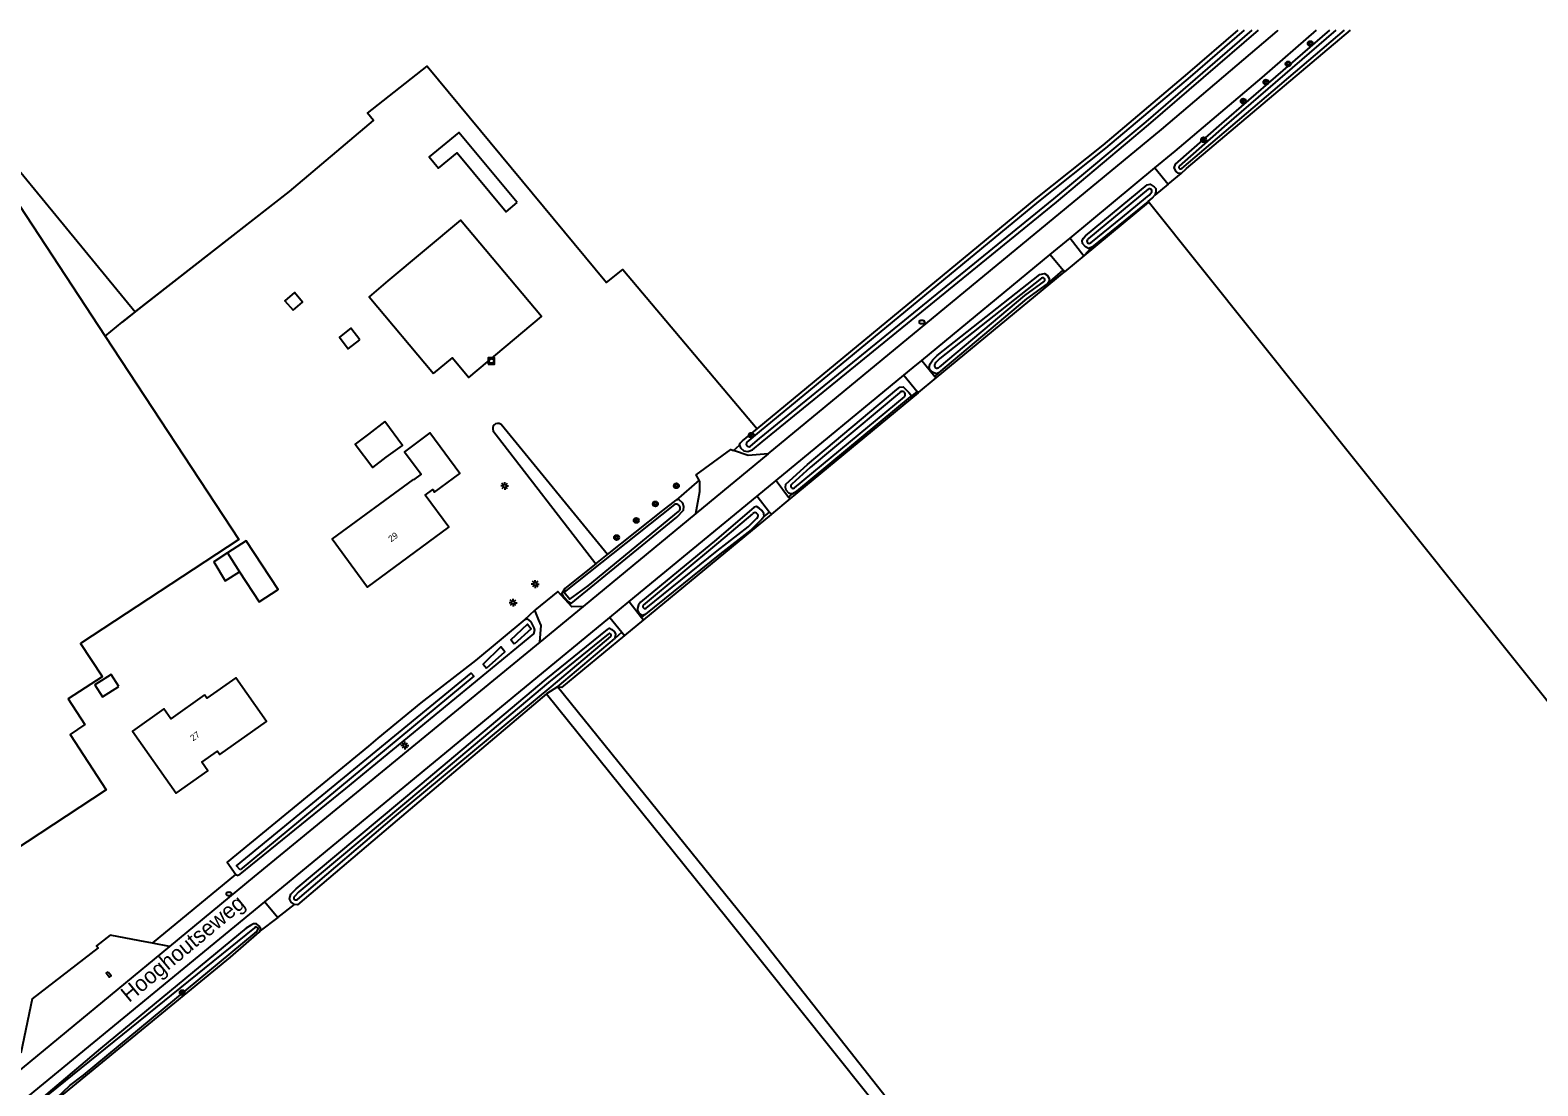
# Model space of a CAD drawing. Extents: x 141000 to 143000, y 400580 to 403500.
# Drawn here: x 142087.7 to 142326.5, y 403332.7 to 403500 of the extents above; entities that cross this region are included whole.
import ezdxf

# ---------------------------------------------------------------- set-up
doc = ezdxf.new("R2010")
doc.units = 0
for name, color, linetype in [('gg-afsc-erfafscheiding', 7, 'Continuous'), ('gg-afsc-hekwerk', 7, 'Continuous'), ('gg-anno-huisnummerreeks BGT', 7, 'Continuous'), ('gg-anno-openbare ruimte label', 7, 'Continuous'), ('gg-bbg-bijgebouw', 7, 'Continuous'), ('gg-bbg-hoofdgebouw', 7, 'Continuous'), ('gg-bbg-luifel en loopbrug', 7, 'Continuous'), ('gg-bbg-overig bouwwerk', 7, 'Continuous'), ('gg-knt-bronhoudergrens', 7, 'Continuous'), ('gg-knt-onverhard', 7, 'Continuous'), ('gg-knt-verharding', 7, 'Continuous'), ('gg-knt-verharding nz', 7, 'Continuous'), ('gg-kntw-bovenkant insteek waterloop', 7, 'Continuous'), ('gg-kntw-waterlijn', 7, 'Continuous'), ('gt-grn-groengrens', 7, 'Continuous'), ('gt-symb-boom', 7, 'Continuous'), ('gt-symb-brandkraan', 7, 'Continuous'), ('gt-symb-kolk center center', 7, 'Continuous'), ('gt-symb-lichtmast', 7, 'Continuous'), ('gt-symb-rioolschacht', 7, 'Continuous')]:
    doc.layers.add(name, color=color, linetype=linetype)

# ---------------------------------------------------------------- blocks, each defined once
blk = doc.blocks.new('gt0-BOOM')
at = {"layer": 'gt-symb-boom'}
for radius in [0.4, 0.2]:
    blk.add_circle((0, 0), radius, dxfattribs=at)
blk = doc.blocks.new('gt0-BR')
at = {"layer": 'gt-symb-brandkraan'}
for centre, radius, start, end in [((-0.24, 0), 0.206, 107.5669, 252.4331), ((0.6, -2.66), 3, 106.892, 107.5669), ((0, -0.69), 0.938, 73.108, 106.892), ((-0.6, -2.66), 3, 72.4331, 73.108), ((0.24, 0), 0.206, 287.567, 72.4331), ((0.6, 2.66), 3, 252.4331, 253.108), ((0, 0.69), 0.938, 253.108, 286.8921), ((-0.6, 2.66), 3, 286.8921, 287.567)]:
    blk.add_arc(centre, radius, start, end, dxfattribs=at)
blk = doc.blocks.new('gt0-RS')
at = {"layer": 'gt-symb-rioolschacht'}
blk.add_lwpolyline([(-0.5, -0.5), (0.5, -0.5), (0.5, 0.5), (-0.5, 0.5)], close=True, dxfattribs=at)
blk.add_circle((0, 0), 0.375, dxfattribs=at)
blk = doc.blocks.new('gt0-LMAST')
at = {"layer": 'gt-symb-lichtmast'}
for p, q in [((-0.18, 0.17), (-0.45, 0.44)), ((-0.01, 0.25), (-0.01, 0.62)), ((0.17, 0.17), (0.44, 0.44)), ((-0.26, 0), (-0.63, 0)), ((-0.18, -0.18), (-0.45, -0.45)), ((-0.01, -0.25), (-0.01, -0.63)), ((0.44, -0.45), (0.17, -0.18)), ((0.24, 0), (0.62, 0))]:
    blk.add_line(p, q, dxfattribs=at)
blk.add_circle((-0.01, 0), 0.25, dxfattribs=at)
blk = doc.blocks.new('gt0-KOLKCC')
at = {"layer": 'gt-symb-kolk center center'}
blk.add_lwpolyline([(-0.38, 0.2), (0.38, 0.2), (0.38, -0.2), (-0.38, -0.2)], close=True, dxfattribs=at)

msp = doc.modelspace()

# ---------------------------------------------------------------- linework, layer by layer
at = {"layer": 'gg-afsc-erfafscheiding'}
for p, q in [((142104.3, 403455.35), (142102.23, 403453.74)), ((142099.57, 403451.49), (142102.23, 403453.74)), ((142199.08, 403433.4), (142200.05, 403434.24)), ((142193.63, 403428.69), (142189.99, 403425.54)), ((142171.9, 403410.75), (142171.72, 403410.56)), ((142166.05, 403406.62), (142167.62, 403408.1))]:
    msp.add_line(p, q, dxfattribs=at)
at = {"layer": 'gg-afsc-hekwerk'}
for p, q in [((142102.23, 403453.74), (142128.76, 403474.43)), ((142264.76, 403472.67), (142254.57, 403464.23)), ((142254.57, 403464.23), (142251.54, 403461.72)), ((142228.32, 403442.56), (142208.04, 403425.74)), ((142208.04, 403425.74), (142205.09, 403423.3)), ((142184.83, 403406.55), (142181.83, 403404.07)), ((142181.83, 403404.07), (142171.86, 403395.83)), ((142107.06, 403355.32), (142120.24, 403366.21)), ((142107.06, 403355.32), (142105.02, 403355.7))]:
    msp.add_line(p, q, dxfattribs=at)
for points in [[(142251.54, 403461.72), (142251.44, 403461.64), (142231.17, 403444.91)], [(142231.17, 403444.91), (142228.34, 403442.58), (142228.32, 403442.56)], [(142205.09, 403423.3), (142205.05, 403423.27), (142184.83, 403406.55)], [(142142.75, 403387.82), (142141.26, 403386.57), (142118.87, 403368.2), (142120.24, 403366.21)], [(142105.02, 403355.7), (142100.36, 403356.59), (142098.19, 403354.93), (142098.46, 403354.58), (142087.98, 403346.52), (142086.18, 403337.91)]]:
    msp.add_lwpolyline(points, dxfattribs=at)
at = {"layer": 'gg-bbg-bijgebouw'}
for points in [[(142062.5, 403500), (142067.6, 403492.19), (142071.26, 403494.59), (142099.57, 403451.49)], [(142151.56, 403445.59), (142154.55, 403448.1), (142157.16, 403444.98), (142168.67, 403454.63), (142155.85, 403469.92), (142144.34, 403460.27), (142141.36, 403457.76), (142151.56, 403445.59)], [(142099.57, 403451.49), (142120.71, 403419.3), (142095.64, 403402.84), (142099.01, 403397.69), (142099.1, 403397.55), (142093.7, 403394.06), (142096.34, 403389.97), (142094, 403388.42), (142099.72, 403379.66), (142085.01, 403369.97)]]:
    msp.add_lwpolyline(points, dxfattribs=at)
at = {"layer": 'gg-bbg-hoofdgebouw'}
for points in [[(142148.41, 403428.75), (142148.36, 403428.83), (142135.49, 403419.38), (142141.13, 403411.73), (142154.01, 403421.26), (142150.26, 403426.33), (142151.44, 403427.2), (142151.73, 403426.8), (142155.75, 403429.77), (142151.01, 403436.18), (142146.99, 403433.2), (142149.61, 403429.63), (142148.41, 403428.75)], [(142115.28, 403394.67), (142109.94, 403390.9), (142108.84, 403392.46), (142103.87, 403388.95), (142110.82, 403379.11), (142115.83, 403382.65), (142114.87, 403384.01), (142117.36, 403385.77), (142117.73, 403385.26), (142125.1, 403390.46), (142120.23, 403397.36), (142115.65, 403394.14), (142115.28, 403394.67)]]:
    msp.add_lwpolyline(points, dxfattribs=at)
at = {"layer": 'gg-bbg-luifel en loopbrug'}
msp.add_line((142118.92, 403417.17), (142120.84, 403414.17), dxfattribs=at)
for points in [[(142143.84, 403437.99), (142141.26, 403435.99), (142139.15, 403434.39), (142141.96, 403430.71), (142144.06, 403432.32), (142146.65, 403434.2), (142143.84, 403437.99)], [(142120.84, 403414.17), (142123.95, 403409.42), (142126.94, 403411.38), (142121.88, 403419.11), (142118.92, 403417.17)], [(142101.7, 403396.03), (142100.48, 403397.92), (142097.91, 403396.26), (142099.13, 403394.37), (142101.7, 403396.03)]]:
    msp.add_lwpolyline(points, dxfattribs=at)
at = {"layer": 'gg-bbg-overig bouwwerk'}
for points in [[(142164.83, 403472.7), (142155.56, 403483.81), (142150.89, 403479.92), (142152.38, 403478.13), (142155.3, 403480.57), (142163.08, 403471.24), (142164.83, 403472.7)], [(142129.31, 403455.61), (142130.83, 403456.92), (142129.53, 403458.43), (142128.01, 403457.13), (142129.31, 403455.61)], [(142139.89, 403450.94), (142138.48, 403452.76), (142136.66, 403451.35), (142138.07, 403449.53), (142139.89, 403450.94)], [(142118.92, 403417.17), (142116.74, 403415.78), (142118.54, 403412.77), (142120.84, 403414.17)]]:
    msp.add_lwpolyline(points, dxfattribs=at)
at = {"layer": 'gg-knt-bronhoudergrens'}
for p, q in [((142267.97, 403475.62), (142270.02, 403477.29)), ((142267.97, 403475.62), (142265.84, 403473.88)), ((142126.89, 403359.42), (142129.54, 403361.45)), ((142126.89, 403359.42), (142124.12, 403357.3))]:
    msp.add_line(p, q, dxfattribs=at)
for points in [[(142067.55, 403500), (142071.16, 403495.73), (142104.3, 403455.35)], [(142104.3, 403455.35), (142128.76, 403474.43), (142142.04, 403485.67), (142141.1, 403486.87), (142150.58, 403494.27), (142178.95, 403460.04), (142181.56, 403462.09), (142202.82, 403436.84)]]:
    msp.add_lwpolyline(points, dxfattribs=at)
at = {"layer": 'gg-knt-onverhard'}
msp.add_line((142370.19, 403340.85), (142264.78, 403472.87), dxfattribs=at)
at = {"layer": 'gg-knt-verharding'}
for p, q in [((142252.42, 403467.06), (142265.86, 403478.17)), ((142252.42, 403467.06), (142254.57, 403464.23)), ((142228.95, 403447.67), (142249.28, 403464.48)), ((142249.28, 403464.48), (142251.33, 403461.97)), ((142251.54, 403461.72), (142251.33, 403461.97)), ((142228.95, 403447.67), (142230.98, 403445.15)), ((142205.86, 403428.65), (142226.09, 403445.32)), ((142226.09, 403445.32), (142228.17, 403442.74)), ((142230.98, 403445.15), (142231.17, 403444.91)), ((142228.32, 403442.56), (142228.17, 403442.74)), ((142205.86, 403428.65), (142207.82, 403426.03)), ((142182.58, 403409.48), (142202.83, 403426.16)), ((142202.83, 403426.16), (142204.82, 403423.64)), ((142208.04, 403425.74), (142207.82, 403426.03)), ((142193.14, 403423.4), (142175.25, 403408.66)), ((142205.09, 403423.3), (142204.82, 403423.64)), ((142182.58, 403409.48), (142184.53, 403406.94)), ((142124.83, 403361.92), (142179.48, 403406.93)), ((142179.48, 403406.93), (142181.38, 403404.61)), ((142184.53, 403406.94), (142184.83, 403406.55)), ((142181.38, 403404.61), (142181.83, 403404.07)), ((142109.74, 403354.81), (142085.2, 403334.54)), ((142109.74, 403354.81), (142107.06, 403355.32))]:
    msp.add_line(p, q, dxfattribs=at)
for points in [[(142204.59, 403432.85), (142266.9, 403484.26), (142285.21, 403499.86), (142285.37, 403500)], [(142265.86, 403478.17), (142269.08, 403480.83), (142282.83, 403492.51), (142291.43, 403500)], [(142193.63, 403428.69), (142193.17, 403429.53), (142198.66, 403433.54), (142199.08, 403433.4)], [(142204.59, 403432.85), (142201.39, 403432.63), (142199.08, 403433.4)], [(142193.14, 403423.4), (142193.76, 403426.89), (142193.75, 403428.47), (142193.63, 403428.69)], [(142171.72, 403410.56), (142171.27, 403411.05), (142167.62, 403408.1)], [(142175.25, 403408.66), (142173.49, 403408.65), (142172.45, 403409.77), (142171.72, 403410.56)], [(142168.42, 403403.04), (142168.6, 403405.68), (142168.27, 403406.5), (142167.62, 403408.1)], [(142168.42, 403403.04), (142123.17, 403365.89), (142109.74, 403354.81)], [(142014.82, 403271.27), (142047.98, 403298.49), (142087.43, 403331.11), (142124.83, 403361.92)]]:
    msp.add_lwpolyline(points, dxfattribs=at)
at = {"layer": 'gg-knt-verharding nz'}
for p, q in [((142249.28, 403464.48), (142252.42, 403467.06)), ((142204.59, 403432.85), (142193.14, 403423.4)), ((142202.83, 403426.16), (142205.86, 403428.65)), ((142179.48, 403406.93), (142182.58, 403409.48)), ((142175.25, 403408.66), (142168.42, 403403.04))]:
    msp.add_line(p, q, dxfattribs=at)
msp.add_lwpolyline([(142226.09, 403445.32), (142227.56, 403446.53), (142228.95, 403447.67)], dxfattribs=at)
at = {"layer": 'gg-kntw-bovenkant insteek waterloop'}
for p, q in [((142179.15, 403416.93), (142162.27, 403437.54)), ((142160.99, 403436.56), (142177.26, 403415.44)), ((142171.21, 403395.96), (142180.24, 403403.55)), ((142120.24, 403366.21), (142120.61, 403366.05))]:
    msp.add_line(p, q, dxfattribs=at)
for points in [[(142200.05, 403434.24), (142200.22, 403433.84), (142200.71, 403433.36), (142201.36, 403433.23), (142202.09, 403433.52), (142203.64, 403434.8), (142250.26, 403472.75), (142264.86, 403484.99), (142282.24, 403500)], [(142202.82, 403436.84), (142247.03, 403473.35), (142257.67, 403481.79), (142271.08, 403493.12), (142279.05, 403500)], [(142270.02, 403477.29), (142269.53, 403477.34), (142269.21, 403477.63), (142268.9, 403478.18), (142269.12, 403478.78), (142276.47, 403485.2), (142293.56, 403500)], [(142270.02, 403477.29), (142270.87, 403478.06), (142296.85, 403500)], [(142255.86, 403465.6), (142255.31, 403465.4), (142254.88, 403465.69), (142254.37, 403466.2), (142254.32, 403466.67), (142254.55, 403467.05), (142254.84, 403467.43), (142264.63, 403475.5), (142265.08, 403475.58), (142265.74, 403475.2), (142266.01, 403474.9), (142266.01, 403474.37), (142265.84, 403473.88)], [(142264.78, 403472.87), (142265.39, 403473.38), (142265.84, 403473.88)], [(142264.78, 403472.87), (142261.14, 403469.88), (142255.86, 403465.6)], [(142231.62, 403445.71), (142231.18, 403445.57), (142230.61, 403445.83), (142230.21, 403446.26), (142230.08, 403446.62), (142230.23, 403447.15), (142230.65, 403447.74), (142231.35, 403448.45), (142247.62, 403461.31), (142248.34, 403461.46), (142248.76, 403461.17), (142249.08, 403460.66), (142249.1, 403460.23), (142248.84, 403459.81)], [(142231.62, 403445.71), (142245.58, 403457.44), (142248.84, 403459.81)], [(142208.49, 403426.57), (142208.13, 403426.51), (142207.87, 403426.66), (142207.45, 403427.11), (142207.35, 403427.55), (142207.38, 403428.08), (142210.79, 403431.2), (142224.98, 403443.04), (142225.45, 403443.41), (142225.96, 403443.47), (142226.87, 403442.61), (142227.16, 403442.21), (142227.14, 403441.89)], [(142208.49, 403426.57), (142209.11, 403426.94), (142227.14, 403441.89)], [(142200.05, 403434.24), (142200.13, 403434.55), (142200.52, 403434.95), (142202.82, 403436.84)], [(142171.9, 403410.75), (142172.11, 403410.33), (142172.96, 403409.43), (142173.36, 403409.15), (142190.09, 403422.85), (142191.16, 403423.94), (142191.24, 403424.53), (142191.04, 403425.07), (142190.44, 403425.66), (142189.99, 403425.54)], [(142179.15, 403416.93), (142187.9, 403423.88), (142189.99, 403425.54)], [(142203.95, 403422.95), (142203.91, 403423.44), (142203.59, 403423.87), (142203.18, 403424.26), (142202.71, 403424.54), (142202.34, 403424.43), (142196.38, 403419.32), (142184.34, 403409.36), (142184.06, 403408.96), (142183.88, 403408.39), (142183.86, 403408.03), (142184.15, 403407.6), (142184.55, 403407.29), (142185.13, 403407.46)], [(142203.95, 403422.95), (142203.58, 403422.53), (142201.87, 403420.84), (142196.92, 403416.98), (142185.13, 403407.46)], [(142177.26, 403415.44), (142172.35, 403411.55), (142171.9, 403410.75)], [(142166.05, 403406.62), (142166.39, 403406.74), (142166.96, 403406.23), (142167.48, 403405.33), (142167.57, 403404.91), (142167.4, 403404.34), (142137.62, 403379.87), (142120.61, 403366.05)], [(142166.05, 403406.62), (142158.21, 403400.13), (142149.54, 403393.43), (142142.75, 403387.82)], [(142129.54, 403361.45), (142129.02, 403361.82), (142128.76, 403362.36), (142128.97, 403363.1), (142129.81, 403363.95), (142149.46, 403380.39), (142169.39, 403397.16), (142179.12, 403405.04), (142179.46, 403405.23), (142179.84, 403405.04), (142180.24, 403404.69), (142180.39, 403404.31), (142180.34, 403403.91), (142180.24, 403403.55)], [(142169.48, 403394.83), (142145.83, 403374.84), (142130.02, 403361.42), (142129.54, 403361.45)], [(142169.48, 403394.83), (142198.06, 403359.34), (142237.14, 403310.36), (142263.69, 403277.34), (142273.33, 403265.7)], [(142274.3, 403266.38), (142266.23, 403276.46), (142203.01, 403356.63), (142171.21, 403395.96)], [(142124.12, 403357.3), (142124.19, 403357.64), (142123.96, 403358.05), (142123.54, 403358.39), (142123.06, 403358.39), (142122.56, 403358.17), (142121.9, 403357.7), (142098.81, 403338.68), (142088.77, 403330.13), (142088.71, 403329.77), (142088.71, 403329.4), (142089.21, 403328.91), (142089.57, 403328.86)], [(142092.36, 403330.94), (142119.43, 403353.14), (142123.93, 403357.07), (142124.12, 403357.3)]]:
    msp.add_lwpolyline(points, dxfattribs=at)
for centre, start, end in [((142161.77, 403436.87), 53.0483, 137.3127), ((142161.77, 403436.88), 137.3421, 201.9793)]:
    msp.add_arc(centre, 0.834, start, end, dxfattribs=at)
at = {"layer": 'gg-kntw-waterlijn'}
for p, q in [((142270.1, 403478.08), (142295.87, 403500)), ((142208.74, 403427.47), (142226.16, 403441.92)), ((142177.26, 403415.44), (142179.15, 403416.93)), ((142171.21, 403395.96), (142169.48, 403394.83))]:
    msp.add_line(p, q, dxfattribs=at)
for points in [[(142201.27, 403434.72), (142203.23, 403436.34), (142247.44, 403472.84), (142258.08, 403481.28), (142271.5, 403492.62), (142280.05, 403500)], [(142201.76, 403434.08), (142203.23, 403435.31), (142249.85, 403473.25), (142264.44, 403485.49), (142281.24, 403500)], [(142269.73, 403478.45), (142276.9, 403484.71), (142294.55, 403500)], [(142264.77, 403474.78), (142255.31, 403466.98), (142255.19, 403466.82)], [(142255.68, 403466.29), (142260.73, 403470.39), (142264.37, 403473.38), (142264.94, 403473.85), (142265.27, 403474.22)], [(142247.91, 403460.7), (142231.78, 403447.96), (142231.15, 403447.32), (142231.05, 403447.17)], [(142248.29, 403460.21), (142245.18, 403457.95), (142231.65, 403446.59)], [(142225.47, 403442.6), (142225.39, 403442.54), (142211.22, 403430.71), (142208.33, 403428.07)], [(142189.74, 403424.84), (142172.29, 403410.96), (142173.18, 403409.86), (142176.05, 403411.94), (142190.38, 403423.74)], [(142184.82, 403408.92), (142196.79, 403418.82), (142202.13, 403423.39)], [(142185.28, 403408.42), (142196.52, 403417.49), (142201.44, 403421.33), (142202.78, 403422.66)], [(142179.25, 403404.31), (142169.8, 403396.66), (142149.88, 403379.9), (142130.25, 403363.47), (142129.55, 403362.76)], [(142164.36, 403402.74), (142163.84, 403403.38), (142166.48, 403405.86), (142167.03, 403405.16), (142164.36, 403402.74)], [(142130.02, 403362.28), (142145.41, 403375.34), (142170.22, 403395.98), (142179.67, 403403.92)], [(142159.96, 403398.94), (142162.86, 403401.48), (142162.22, 403402.28), (142159.43, 403399.55), (142159.96, 403398.94)], [(142120.92, 403366.94), (142120.34, 403367.61), (142157.51, 403398.14), (142157.96, 403397.65), (142120.92, 403366.94)], [(142096.1, 403334.45), (142123.22, 403356.86), (142123.61, 403357.26), (142123.78, 403357.62), (142123.65, 403357.83), (142123.46, 403357.94), (142123.21, 403357.8), (142090.46, 403331.3), (142089.21, 403330.03), (142089.15, 403329.71), (142089.46, 403329.37), (142090.17, 403329.49), (142090.47, 403329.64), (142091.19, 403330.18), (142091.91, 403330.85), (142093.98, 403332.79), (142096.1, 403334.45)]]:
    msp.add_lwpolyline(points, dxfattribs=at)
for centre, radius, start, end in [((142269.91, 403478.26), 0.264, 133.2482, 315.0645), ((142265.01, 403474.49), 0.375, 313.8261, 129.8983), ((142255.45, 403466.57), 0.362, 135.6563, 310.6413), ((142248.11, 403460.47), 0.313, 304.7864, 130.5296), ((142231.35, 403446.88), 0.421, 136.0524, 316.6433), ((142225.82, 403442.27), 0.484, 314.2549, 136.2477), ((142201.5, 403434.39), 0.401, 125.0389, 310.4729), ((142208.51, 403427.75), 0.36, 118.9608, 309.0845), ((142190.01, 403424.26), 0.64, 47.9129, 115.0256), ((142190.01, 403424.26), 0.641, 305.5931, 47.8626), ((142202.49, 403423.06), 0.495, 306.0736, 136.9327), ((142185.06, 403408.68), 0.337, 135.6112, 310.4224), ((142179.46, 403404.12), 0.285, 315.3683, 138.4737), ((142129.77, 403362.51), 0.337, 131.108, 316.9662)]:
    msp.add_arc(centre, radius, start, end, dxfattribs=at)
at = {"layer": 'gt-grn-groengrens'}
for p, q in [((142265.86, 403478.17), (142267.97, 403475.62)), ((142264.76, 403472.67), (142264.78, 403472.87)), ((142255.86, 403465.6), (142254.57, 403464.23)), ((142248.84, 403459.81), (142251.33, 403461.97)), ((142231.62, 403445.71), (142230.98, 403445.15)), ((142228.17, 403442.74), (142227.14, 403441.89)), ((142207.82, 403426.03), (142208.49, 403426.57)), ((142203.95, 403422.95), (142204.82, 403423.64)), ((142184.53, 403406.94), (142185.13, 403407.46)), ((142181.38, 403404.61), (142180.24, 403403.55)), ((142171.86, 403395.83), (142171.21, 403395.96)), ((142124.83, 403361.92), (142126.89, 403359.42))]:
    msp.add_line(p, q, dxfattribs=at)

# ---------------------------------------------------------------- block references
at = {"layer": 'gt-symb-boom'}
for p in [(142290.47, 403497.88), (142286.96, 403494.65), (142283.44, 403491.77), (142279.84, 403488.77), (142273.56, 403482.64), (142201.92, 403435.81), (142190.05, 403427.81), (142186.72, 403424.94), (142183.68, 403422.33), (142180.58, 403419.61), (142111.77, 403347.51)]:
    msp.add_blockref('gt0-BOOM', p, dxfattribs=at)
at = {"layer": 'gt-symb-brandkraan'}
for p in [(142228.93, 403453.75), (142119.15, 403363.16)]:
    msp.add_blockref('gt0-BR', p, dxfattribs=at)
at = {"layer": 'gt-symb-kolk center center', "rotation": -52.76696495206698}
msp.add_blockref('gt0-KOLKCC', (142100.11, 403350.39), dxfattribs=at)
at = {"layer": 'gt-symb-lichtmast'}
for p in [(142162.85, 403427.78), (142167.68, 403412.24), (142164.18, 403409.29), (142147.03, 403386.67)]:
    msp.add_blockref('gt0-LMAST', p, dxfattribs=at)
at = {"layer": 'gt-symb-rioolschacht'}
msp.add_blockref('gt0-RS', (142160.73, 403447.59), dxfattribs=at)

# ---------------------------------------------------------------- texts
at = {"layer": 'gg-anno-huisnummerreeks BGT'}
for s, rotation, p in [('29', 36.5, (142144.86, 403418.85)), ('27', 35.3, (142113.46, 403387.3))]:
    msp.add_text(s, height=1, rotation=rotation, dxfattribs=at).set_placement(p)
at = {"layer": 'gg-anno-openbare ruimte label'}
msp.add_text('Hooghoutseweg', height=2.5, rotation=39.7, dxfattribs=at).set_placement((142103.34, 403345.85))

doc.saveas('drawing.dxf')
